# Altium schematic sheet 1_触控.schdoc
size 309 x 223 mm; Symbol: Sheet-Symbol_A4; Device: Sheet-Symbol_A4; Company: 嘉立创EDA; Version: V1.0; Page Size: A4; @Project Name: 电容触摸键盘-第一验证板; @Page Count: 1; @Update Date: 2024-10-14; @Create Date: 2024-10-14; @Schematic Name: Schematic1; @Page No: 1; @Page Name: P1; @Board Name: Board1; @Create Time: 22:22:40; @Update Time: 22:22:40
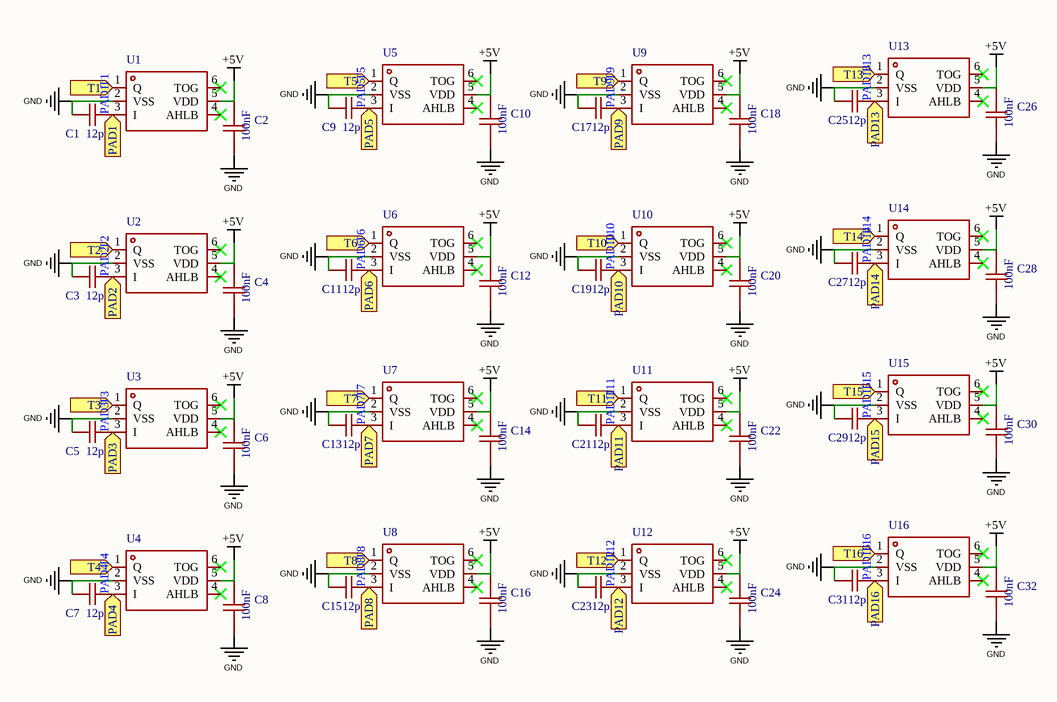
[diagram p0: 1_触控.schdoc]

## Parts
C1  12pF  [C0603]
C2  100nF  [C0603]
C3  12pF  [C0603]
C4  100nF  [C0603]
C5  12pF  [C0603]
C6  100nF  [C0603]
C7  12pF  [C0603]
C8  100nF  [C0603]
C9  12pF  [C0603]
C10  100nF  [C0603]
C11  12pF  [C0603]
C12  100nF  [C0603]
C13  12pF  [C0603]
C14  100nF  [C0603]
C15  12pF  [C0603]
C16  100nF  [C0603]
C17  12pF  [C0603]
C18  100nF  [C0603]
C19  12pF  [C0603]
C20  100nF  [C0603]
C21  12pF  [C0603]
C22  100nF  [C0603]
C23  12pF  [C0603]
C24  100nF  [C0603]
C25  12pF  [C0603]
C26  100nF  [C0603]
C27  12pF  [C0603]
C28  100nF  [C0603]
C29  12pF  [C0603]
C30  100nF  [C0603]
C31  12pF  [C0603]
C32  100nF  [C0603]
U1  TTP223E-HA6  [SOT-23-6_L2.9-W1.6-P0.95-LS2.8-BR]  (value not drawn)
U2  TTP223E-HA6  [SOT-23-6_L2.9-W1.6-P0.95-LS2.8-BR]  (value not drawn)
U3  TTP223E-HA6  [SOT-23-6_L2.9-W1.6-P0.95-LS2.8-BR]  (value not drawn)
U4  TTP223E-HA6  [SOT-23-6_L2.9-W1.6-P0.95-LS2.8-BR]  (value not drawn)
U5  TTP223E-HA6  [SOT-23-6_L2.9-W1.6-P0.95-LS2.8-BR]  (value not drawn)
U6  TTP223E-HA6  [SOT-23-6_L2.9-W1.6-P0.95-LS2.8-BR]  (value not drawn)
U7  TTP223E-HA6  [SOT-23-6_L2.9-W1.6-P0.95-LS2.8-BR]  (value not drawn)
U8  TTP223E-HA6  [SOT-23-6_L2.9-W1.6-P0.95-LS2.8-BR]  (value not drawn)
U9  TTP223E-HA6  [SOT-23-6_L2.9-W1.6-P0.95-LS2.8-BR]  (value not drawn)
U10  TTP223E-HA6  [SOT-23-6_L2.9-W1.6-P0.95-LS2.8-BR]  (value not drawn)
U11  TTP223E-HA6  [SOT-23-6_L2.9-W1.6-P0.95-LS2.8-BR]  (value not drawn)
U12  TTP223E-HA6  [SOT-23-6_L2.9-W1.6-P0.95-LS2.8-BR]  (value not drawn)
U13  TTP223E-HA6  [SOT-23-6_L2.9-W1.6-P0.95-LS2.8-BR]  (value not drawn)
U14  TTP223E-HA6  [SOT-23-6_L2.9-W1.6-P0.95-LS2.8-BR]  (value not drawn)
U15  TTP223E-HA6  [SOT-23-6_L2.9-W1.6-P0.95-LS2.8-BR]  (value not drawn)
U16  TTP223E-HA6  [SOT-23-6_L2.9-W1.6-P0.95-LS2.8-BR]  (value not drawn)

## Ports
PAD1 (in), PAD2 (in), PAD3 (in), PAD4 (in), PAD5 (in), PAD6 (in), PAD7 (in), PAD8 (in), PAD9 (in), PAD10 (in), PAD11 (in), PAD12 (in), PAD13 (in), PAD14 (in), PAD15 (in), PAD16 (in), T1 (in), T2 (in), T3 (in), T4 (in), T5 (in), T6 (in), T7 (in), T8 (in), T9 (in), T10 (in), T11 (in), T12 (in), T13 (in), T14 (in), T15 (in), T16 (in)

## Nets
+5V: C2.1 C4.1 C6.1 C8.1 C10.1 C12.1 C14.1 C16.1 C18.1 C20.1 C22.1 C24.1 C26.1 C28.1 C30.1 C32.1 U1.5(VDD) U2.5(VDD) U3.5(VDD) U4.5(VDD) U5.5(VDD) U6.5(VDD) U7.5(VDD) U8.5(VDD) U9.5(VDD) U10.5(VDD) U11.5(VDD) U12.5(VDD) U13.5(VDD) U14.5(VDD) U15.5(VDD) U16.5(VDD)
GND: C1.2 C2.2 C3.2 C4.2 C5.2 C6.2 C7.2 C8.2 C9.2 C10.2 C11.2 C12.2 C13.2 C14.2 C15.2 C16.2 C17.2 C18.2 C19.2 C20.2 C21.2 C22.2 C23.2 C24.2 C25.2 C26.2 C27.2 C28.2 C29.2 C30.2 C31.2 C32.2 U1.2(VSS) U2.2(VSS) U3.2(VSS) U4.2(VSS) U5.2(VSS) U6.2(VSS) U7.2(VSS) U8.2(VSS) U9.2(VSS) U10.2(VSS) U11.2(VSS) U12.2(VSS) U13.2(VSS) U14.2(VSS) U15.2(VSS) U16.2(VSS)
PAD1: C1.1 U1.3(I) ; port PAD1
PAD2: C3.1 U2.3(I) ; port PAD2
PAD3: C5.1 U3.3(I) ; port PAD3
PAD4: C7.1 U4.3(I) ; port PAD4
PAD5: C9.1 U5.3(I) ; port PAD5
PAD6: C11.1 U6.3(I) ; port PAD6
PAD7: C13.1 U7.3(I) ; port PAD7
PAD8: C15.1 U8.3(I) ; port PAD8
PAD9: C17.1 U9.3(I) ; port PAD9
PAD10: C19.1 U10.3(I) ; port PAD10
PAD11: C21.1 U11.3(I) ; port PAD11
PAD12: C23.1 U12.3(I) ; port PAD12
PAD13: C25.1 U13.3(I) ; port PAD13
PAD14: C27.1 U14.3(I) ; port PAD14
PAD15: C29.1 U15.3(I) ; port PAD15
PAD16: C31.1 U16.3(I) ; port PAD16
T1: U1.1(Q) ; port T1
T2: U2.1(Q) ; port T2
T3: U3.1(Q) ; port T3
T4: U4.1(Q) ; port T4
T5: U5.1(Q) ; port T5
T6: U6.1(Q) ; port T6
T7: U7.1(Q) ; port T7
T8: U8.1(Q) ; port T8
T9: U9.1(Q) ; port T9
T10: U10.1(Q) ; port T10
T11: U11.1(Q) ; port T11
T12: U12.1(Q) ; port T12
T13: U13.1(Q) ; port T13
T14: U14.1(Q) ; port T14
T15: U15.1(Q) ; port T15
T16: U16.1(Q) ; port T16

Not connected (* = marked no-connect by the designer): U1 4(AHLB)* 6(TOG)*; U2 4(AHLB)* 6(TOG)*; U3 4(AHLB)* 6(TOG)*; U4 4(AHLB)* 6(TOG)*; U5 4(AHLB)* 6(TOG)*; U6 4(AHLB)* 6(TOG)*; U7 4(AHLB)* 6(TOG)*; U8 4(AHLB)* 6(TOG)*; U9 4(AHLB)* 6(TOG)*; U10 4(AHLB)* 6(TOG)*; U11 4(AHLB)* 6(TOG)*; U12 4(AHLB)* 6(TOG)*; U13 4(AHLB)* 6(TOG)*; U14 4(AHLB)* 6(TOG)*; U15 4(AHLB)* 6(TOG)*; U16 4(AHLB)* 6(TOG)*

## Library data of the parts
C1 C3 C5 C7 C9 C11 C13 C15 C17 C19 C21 C23 C25 C27 C29 C31 = CL10C120JB8NNNC: 容值:12pF;精度:±5%;额定电压:50V;材质(温度系数):C0G;; Manufacturer: SAMSUNG(三星); Add into BOM: yes; Tolerance: ±5%; Voltage Rated: 50V; Temperature Coefficient: C0G
C2 C4 C6 C8 C10 C12 C14 C16 C18 C20 C22 C24 C26 C28 C30 C32 = CC0603KRX7R9BB104: 容值:100nF;精度:±10%;额定电压:50V;材质(温度系数):X7R;; Manufacturer: YAGEO(国巨); Add into BOM: yes; Tolerance: ±10%; Voltage Rated: 50V; Temperature Coefficient: X7R
U1-U16 = TTP223E-HA6: 单按键触摸感应开关; Manufacturer: TONTEK(通泰); Add into BOM: yes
